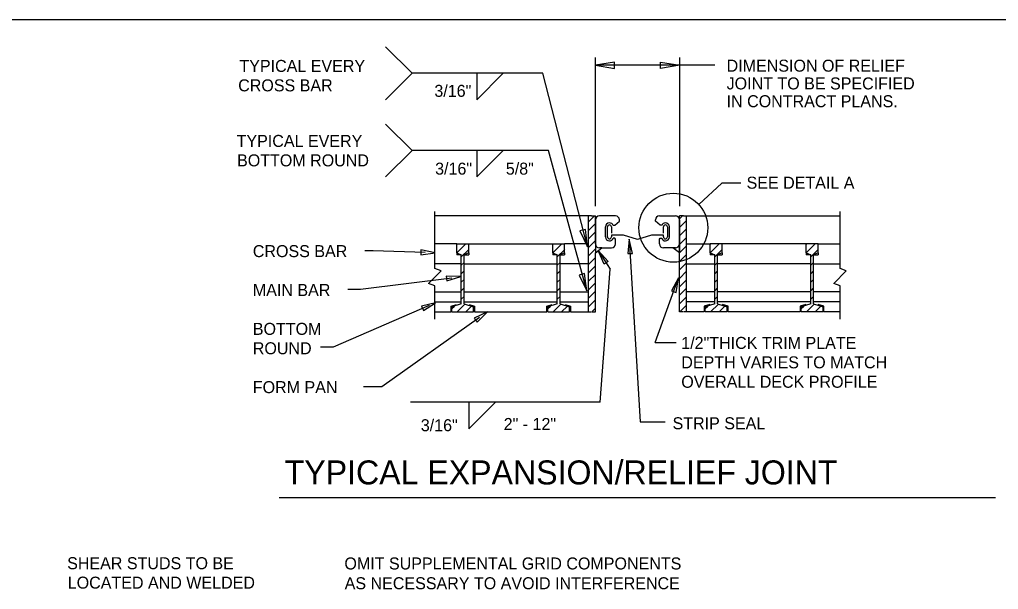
# Model space of a CAD drawing. Extents: x -24512 to -22484, y 4569 to 6351.
# Drawn here: x -24010.5 to -23765.7, y 5598.2 to 5740.6 of the extents above; entities that cross this region are included whole.
import ezdxf

# ---------------------------------------------------------------- set-up
doc = ezdxf.new("R2010")
doc.units = 0
for name, color, linetype in [('10', 7, 'Continuous'), ('2', 7, 'Continuous'), ('3', 7, 'Continuous'), ('4', 7, 'Continuous'), ('9', 7, 'Continuous'), ('PLT-BNDY', 7, 'Continuous')]:
    doc.layers.add(name, color=color, linetype=linetype)

# ---------------------------------------------------------------- blocks, each defined once
blk = doc.blocks.new('SYM026')
at = {"layer": '3'}
for p, q in [((45.29725, 11.51025), (45.748875, 11.96175)), ((45.29725, 11.937875), (45.32125, 11.96175)), ((45.52425, 11.3095), (45.8965, 11.68175)), ((45.52425, 10.881875), (45.6695, 11.027)), ((45.52425, 10.454125), (45.6695, 10.599375)), ((45.52425, 10.0265), (45.6695, 10.171625)), ((45.52425, 9.59875), (45.6695, 9.744)), ((45.31525, 8.534375), (45.7065, 8.925625)), ((45.52425, 9.171125), (45.6695, 9.31625)), ((45.04875, 8.6955), (45.18175, 8.8285)), ((45.743, 8.534375), (46.031, 8.8225))]:
    blk.add_line(p, q, dxfattribs=at)

msp = doc.modelspace()

# ---------------------------------------------------------------- linework, layer by layer
at = {"layer": '10'}
for p, q in [((-23840.65, 5694.43), (-23834.85, 5699.76)), ((-23866.47, 5684.57), (-23866.47, 5682.32)), ((-23845.47, 5684.57), (-23845.47, 5682.32)), ((-23866.47, 5682.32), (-23864.86, 5683.57)), ((-23864.86, 5683.57), (-23865.47, 5683.57)), ((-23845.47, 5682.32), (-23847.08, 5683.57)), ((-23847.08, 5683.57), (-23846.47, 5683.57)), ((-23945.53, 5621.13), (-23766.44, 5621.13))]:
    msp.add_line(p, q, dxfattribs=at)
msp.add_circle((-23847, 5688.6), 8.62, dxfattribs=at)
for centre, start, end in [((-23865.47, 5684.57), 180, 270), ((-23846.47, 5684.57), 270, 0)]:
    msp.add_arc(centre, 1, start, end, dxfattribs=at)
at = {"layer": '2'}
msp.add_line((-24137.79, 5740.63), (-23353.75, 5740.63), dxfattribs=at)
at = {"layer": '3'}
for p, q in [((-23868.22, 5690.05), (-23866.7, 5691.57)), ((-23845.47, 5690.8), (-23844.7, 5691.57)), ((-23868.22, 5687.93), (-23866.47, 5689.68)), ((-23845.47, 5688.68), (-23843.72, 5690.43)), ((-23868.22, 5685.81), (-23866.47, 5687.56)), ((-23845.47, 5686.56), (-23843.72, 5688.31)), ((-23845.47, 5684.44), (-23843.72, 5686.19)), ((-23868.22, 5683.69), (-23866.47, 5685.44)), ((-23845.47, 5682.32), (-23843.72, 5684.07)), ((-23868.22, 5681.57), (-23866.47, 5683.32)), ((-23845.47, 5680.2), (-23843.72, 5681.95)), ((-23868.22, 5679.45), (-23866.47, 5681.2)), ((-23868.22, 5677.33), (-23866.47, 5679.08)), ((-23845.47, 5678.08), (-23843.72, 5679.83)), ((-23868.22, 5675.21), (-23866.47, 5676.95)), ((-23845.47, 5675.95), (-23843.72, 5677.71)), ((-23868.22, 5673.08), (-23866.47, 5674.83)), ((-23845.47, 5673.83), (-23843.72, 5675.58)), ((-23868.22, 5670.96), (-23866.47, 5672.71)), ((-23845.47, 5671.71), (-23843.72, 5673.46)), ((-23868.22, 5668.84), (-23866.47, 5670.59)), ((-23845.47, 5669.59), (-23843.72, 5671.34)), ((-23845.37, 5667.57), (-23843.72, 5669.22)), ((-23867.37, 5667.57), (-23866.47, 5668.47))]:
    msp.add_line(p, q, dxfattribs=at)
at = {"layer": '4'}
for p, q in [((-23867.47, 5691.57), (-23906.63, 5691.57)), ((-23868.22, 5667.57), (-23868.22, 5691.57)), ((-23867.47, 5691.57), (-23866.47, 5691.57)), ((-23866.47, 5684.57), (-23866.47, 5691.57)), ((-23844.47, 5691.57), (-23845.47, 5691.57)), ((-23845.47, 5667.57), (-23845.47, 5691.57)), ((-23844.47, 5691.57), (-23805.3, 5691.57)), ((-23843.72, 5667.57), (-23843.72, 5691.57)), ((-23901.14, 5684.57), (-23906.63, 5684.57)), ((-23901.14, 5684.57), (-23898.17, 5684.57)), ((-23901.14, 5682.31), (-23901.14, 5684.57)), ((-23898.17, 5682.31), (-23898.17, 5684.57)), ((-23898.17, 5684.57), (-23877.14, 5684.57)), ((-23877.14, 5682.31), (-23877.14, 5684.57)), ((-23877.14, 5684.57), (-23874.17, 5684.57)), ((-23868.22, 5684.57), (-23874.17, 5684.57)), ((-23874.17, 5682.31), (-23874.17, 5684.57)), ((-23843.72, 5684.57), (-23837.77, 5684.57)), ((-23834.79, 5684.57), (-23837.77, 5684.57)), ((-23837.77, 5682.31), (-23837.77, 5684.57)), ((-23813.77, 5684.57), (-23834.79, 5684.57)), ((-23834.79, 5682.31), (-23834.79, 5684.57)), ((-23813.77, 5682.31), (-23813.77, 5684.57)), ((-23810.8, 5684.57), (-23813.77, 5684.57)), ((-23810.8, 5684.57), (-23805.3, 5684.57)), ((-23810.8, 5682.31), (-23810.8, 5684.57)), ((-23901.14, 5682.31), (-23900.01, 5681.81)), ((-23901.14, 5682.31), (-23901.14, 5681.81)), ((-23900.01, 5681.81), (-23901.14, 5681.81)), ((-23900.01, 5669.57), (-23900.01, 5681.81)), ((-23898.17, 5682.31), (-23899.29, 5681.81)), ((-23899.29, 5669.57), (-23899.29, 5681.81)), ((-23899.29, 5681.81), (-23898.17, 5681.81)), ((-23898.17, 5682.31), (-23898.17, 5681.81)), ((-23877.14, 5682.31), (-23876.01, 5681.81)), ((-23877.14, 5682.31), (-23877.14, 5681.81)), ((-23876.01, 5681.81), (-23877.14, 5681.81)), ((-23876.01, 5669.57), (-23876.01, 5681.81)), ((-23874.17, 5682.31), (-23875.29, 5681.81)), ((-23875.29, 5681.81), (-23874.17, 5681.81)), ((-23875.29, 5669.57), (-23875.29, 5681.81)), ((-23874.17, 5682.31), (-23874.17, 5681.81)), ((-23866.47, 5667.57), (-23866.47, 5682.32)), ((-23837.77, 5682.31), (-23836.64, 5681.81)), ((-23837.77, 5682.31), (-23837.77, 5681.81)), ((-23836.64, 5681.81), (-23837.77, 5681.81)), ((-23836.64, 5669.57), (-23836.64, 5681.81)), ((-23834.79, 5682.31), (-23835.92, 5681.81)), ((-23835.92, 5681.81), (-23834.79, 5681.81)), ((-23835.92, 5669.57), (-23835.92, 5681.81)), ((-23834.79, 5682.31), (-23834.79, 5681.81)), ((-23813.77, 5682.31), (-23813.77, 5681.81)), ((-23813.77, 5682.31), (-23812.64, 5681.81)), ((-23812.64, 5681.81), (-23813.77, 5681.81)), ((-23812.64, 5669.57), (-23812.64, 5681.81)), ((-23810.8, 5682.31), (-23811.92, 5681.81)), ((-23811.92, 5681.81), (-23810.8, 5681.81)), ((-23811.92, 5669.57), (-23811.92, 5681.81)), ((-23810.8, 5682.31), (-23810.8, 5681.81)), ((-23900.01, 5679.57), (-23906.63, 5679.57)), ((-23899.29, 5679.57), (-23876.01, 5679.57)), ((-23868.22, 5679.57), (-23875.29, 5679.57)), ((-23843.72, 5679.57), (-23836.64, 5679.57)), ((-23812.64, 5679.57), (-23835.92, 5679.57)), ((-23811.92, 5679.57), (-23805.3, 5679.57)), ((-23866.47, 5672.98), (-23866.47, 5676.98)), ((-23906.63, 5672.61), (-23900.01, 5672.61)), ((-23906.63, 5665.74), (-23906.63, 5672.61)), ((-23899.29, 5672.61), (-23876.01, 5672.61)), ((-23875.29, 5672.61), (-23868.22, 5672.61)), ((-23836.64, 5672.61), (-23843.72, 5672.61)), ((-23812.64, 5672.61), (-23835.92, 5672.61)), ((-23805.3, 5672.61), (-23811.92, 5672.61)), ((-23805.3, 5665.74), (-23805.3, 5672.61)), ((-23906.63, 5670.11), (-23900.01, 5670.11)), ((-23900.01, 5669.57), (-23902.37, 5668.82)), ((-23899.29, 5670.11), (-23876.01, 5670.11)), ((-23899.29, 5669.57), (-23896.94, 5668.82)), ((-23876.01, 5669.57), (-23878.37, 5668.82)), ((-23875.29, 5670.11), (-23868.22, 5670.11)), ((-23875.29, 5669.57), (-23872.94, 5668.82)), ((-23836.64, 5670.11), (-23843.72, 5670.11)), ((-23836.64, 5669.57), (-23839, 5668.82)), ((-23812.64, 5670.11), (-23835.92, 5670.11)), ((-23835.92, 5669.57), (-23833.56, 5668.82)), ((-23812.64, 5669.57), (-23815, 5668.82)), ((-23805.3, 5670.11), (-23811.92, 5670.11)), ((-23811.92, 5669.57), (-23809.56, 5668.82)), ((-23902.37, 5667.57), (-23902.37, 5668.82)), ((-23902.37, 5667.57), (-23896.94, 5667.57)), ((-23896.94, 5667.57), (-23896.94, 5668.82)), ((-23878.37, 5667.57), (-23878.37, 5668.82)), ((-23878.37, 5667.57), (-23872.94, 5667.57)), ((-23872.94, 5667.57), (-23872.94, 5668.82)), ((-23867.47, 5667.57), (-23866.47, 5667.57)), ((-23844.47, 5667.57), (-23845.47, 5667.57)), ((-23839, 5667.57), (-23839, 5668.82)), ((-23833.56, 5667.57), (-23839, 5667.57)), ((-23833.56, 5667.57), (-23833.56, 5668.82)), ((-23815, 5667.57), (-23815, 5668.82)), ((-23809.56, 5667.57), (-23815, 5667.57)), ((-23809.56, 5667.57), (-23809.56, 5668.82))]:
    msp.add_line(p, q, dxfattribs=at)
for points in [[(-23906.63, 5672.61), (-23906.63, 5674.05), (-23908.18, 5674.7), (-23905.08, 5677.8), (-23906.63, 5678.44), (-23906.63, 5692.67)], [(-23805.3, 5672.61), (-23805.3, 5674.05), (-23806.86, 5674.7), (-23803.75, 5677.8), (-23805.3, 5678.44), (-23805.3, 5692.67)], [(-23906.63, 5667.57), (-23902.54, 5667.57), (-23902.54, 5669), (-23901.19, 5669.43)], [(-23898.04, 5669.43), (-23896.69, 5669), (-23896.69, 5667.57), (-23878.62, 5667.57), (-23878.62, 5669), (-23877.27, 5669.43)], [(-23874.04, 5669.43), (-23872.69, 5669), (-23872.69, 5667.57), (-23867.63, 5667.57)], [(-23837.9, 5669.43), (-23839.25, 5669), (-23839.25, 5667.57), (-23844.31, 5667.57)], [(-23813.9, 5669.43), (-23815.25, 5669), (-23815.25, 5667.57), (-23833.31, 5667.57), (-23833.31, 5669), (-23834.67, 5669.43)], [(-23805.3, 5667.57), (-23809.39, 5667.57), (-23809.39, 5669), (-23810.75, 5669.43)]]:
    msp.add_lwpolyline(points, dxfattribs=at)
at = {"layer": '9'}
for p, q in [((-23918.94, 5733.83), (-23912.32, 5727.21)), ((-23866.47, 5693.97), (-23866.47, 5731.19)), ((-23845.37, 5693.97), (-23845.37, 5731.19)), ((-23836.59, 5729.21), (-23866.47, 5729.21)), ((-23918.94, 5720.59), (-23912.32, 5727.21)), ((-23879.65, 5727.21), (-23912.32, 5727.21)), ((-23896.17, 5720.59), (-23889.55, 5727.21)), ((-23896.17, 5727.21), (-23896.17, 5720.59)), ((-23868.49, 5683.84), (-23879.65, 5727.21)), ((-23918.94, 5714.53), (-23912.32, 5707.91)), ((-23918.94, 5701.29), (-23912.32, 5707.91)), ((-23878.18, 5707.91), (-23912.32, 5707.91)), ((-23896.17, 5707.91), (-23896.17, 5701.29)), ((-23896.17, 5701.29), (-23889.55, 5707.91)), ((-23868.62, 5672.81), (-23878.18, 5707.91)), ((-23830.09, 5699.76), (-23834.85, 5699.76)), ((-23858, 5685.76), (-23855.32, 5640.06)), ((-23922.06, 5682.85), (-23924.18, 5682.85)), ((-23909.03, 5682.4), (-23922.06, 5682.85)), ((-23865.76, 5682.87), (-23862.76, 5678.22)), ((-23865.3, 5644.98), (-23862.76, 5678.22)), ((-23902.4, 5676.02), (-23925.24, 5673.14)), ((-23851.57, 5659.89), (-23845.7, 5676.05)), ((-23925.24, 5673.14), (-23928.42, 5673.14)), ((-23908.05, 5669.16), (-23932.07, 5658.72)), ((-23895.46, 5666.18), (-23919.93, 5648.85)), ((-23851.57, 5659.89), (-23846.25, 5659.89)), ((-23932.07, 5658.72), (-23935.26, 5658.72)), ((-23919.93, 5648.85), (-23924.49, 5648.85)), ((-23865.3, 5644.98), (-23912.75, 5644.98)), ((-23898.1, 5638.36), (-23891.48, 5644.98)), ((-23898.1, 5644.98), (-23898.1, 5638.36)), ((-23855.32, 5640.06), (-23849.07, 5640.06))]:
    msp.add_line(p, q, dxfattribs=at)
for points in [[(-23861.67, 5728.41), (-23861.67, 5730.01), (-23866.47, 5729.21)], [(-23850.17, 5728.41), (-23850.17, 5730.01), (-23845.37, 5729.21)], [(-23868.95, 5688.19), (-23870.34, 5687.81), (-23868.49, 5683.84)], [(-23858.4, 5682.14), (-23857.2, 5682.2), (-23858, 5685.76)], [(-23910.11, 5683.04), (-23910.16, 5681.84), (-23906.54, 5682.31)], [(-23863.31, 5680.17), (-23864.31, 5679.52), (-23865.76, 5682.87)], [(-23903.79, 5676.52), (-23903.64, 5675.32), (-23900.14, 5676.37)], [(-23869.18, 5677.16), (-23870.56, 5676.74), (-23868.62, 5672.81)], [(-23847.43, 5672.84), (-23846.3, 5672.45), (-23845.7, 5676.05)], [(-23909.98, 5668.98), (-23909.51, 5667.88), (-23906.44, 5669.86)], [(-23896.78, 5665.98), (-23896.09, 5665), (-23893.5, 5667.57)]]:
    msp.add_lwpolyline(points, close=True, dxfattribs=at)
at = {"layer": 'PLT-BNDY'}
for p, q in [((-23861.47, 5691.57), (-23865.47, 5691.57)), ((-23850.47, 5691.57), (-23846.47, 5691.57)), ((-23866.47, 5690.57), (-23866.47, 5684.57)), ((-23863.97, 5686.32), (-23863.97, 5688.82)), ((-23863.47, 5686.32), (-23863.47, 5688.82)), ((-23862.47, 5688.82), (-23862.47, 5687.24)), ((-23862.04, 5689.2), (-23861.6, 5689.2)), ((-23861.6, 5689.2), (-23860.47, 5690.24)), ((-23860.47, 5690.24), (-23860.47, 5690.57)), ((-23851.47, 5690.24), (-23851.47, 5690.57)), ((-23850.33, 5689.2), (-23851.47, 5690.24)), ((-23849.9, 5689.2), (-23850.33, 5689.2)), ((-23849.47, 5687.24), (-23849.47, 5688.82)), ((-23848.47, 5688.82), (-23848.47, 5686.32)), ((-23847.97, 5686.32), (-23847.97, 5688.82)), ((-23845.47, 5690.57), (-23845.47, 5684.57)), ((-23859.47, 5686.74), (-23862.47, 5686.74)), ((-23862.47, 5686.74), (-23862.47, 5686.32)), ((-23855.97, 5685.62), (-23859.47, 5686.74)), ((-23852.46, 5686.74), (-23855.97, 5685.62)), ((-23849.47, 5686.74), (-23852.46, 5686.74)), ((-23849.47, 5686.32), (-23849.47, 5686.74)), ((-23861.6, 5685.95), (-23862.04, 5685.95)), ((-23861.47, 5685.78), (-23861.6, 5685.95)), ((-23861.47, 5684.57), (-23861.47, 5685.78)), ((-23850.47, 5685.78), (-23850.33, 5685.95)), ((-23850.47, 5684.57), (-23850.47, 5685.78)), ((-23850.33, 5685.95), (-23849.9, 5685.95)), ((-23864.86, 5683.57), (-23862.47, 5683.57)), ((-23846.47, 5683.57), (-23849.47, 5683.57))]:
    msp.add_line(p, q, dxfattribs=at)
for centre, radius, start, end in [((-23865.47, 5690.57), 1, 90, 180), ((-23861.47, 5690.57), 1, 0, 90), ((-23850.47, 5690.57), 1, 90, 180), ((-23846.47, 5690.57), 1, 0, 90), ((-23862.97, 5688.82), 1, 90, 180), ((-23862.97, 5688.82), 0.5, 90, 180), ((-23862.97, 5688.82), 1, 22.0033, 90), ((-23862.97, 5688.82), 0.5, 0, 90), ((-23848.97, 5688.82), 1, 90, 157.9967), ((-23848.97, 5688.82), 0.5, 90, 180), ((-23848.97, 5688.82), 1, 0, 90), ((-23848.97, 5688.82), 0.5, 0, 90), ((-23862.97, 5686.32), 1, 180, 270), ((-23862.97, 5686.32), 0.5, 180, 270), ((-23862.97, 5686.32), 0.5, 270, 0), ((-23848.97, 5686.32), 0.5, 180, 270), ((-23848.97, 5686.32), 0.5, 270, 0), ((-23848.97, 5686.32), 1, 270, 0), ((-23862.97, 5686.32), 1, 270, 337.9967), ((-23862.47, 5684.57), 1, 270, 0), ((-23849.47, 5684.57), 1, 180, 270), ((-23848.97, 5686.32), 1, 202.0033, 270), ((-23846.47, 5684.57), 1, 270, 0)]:
    msp.add_arc(centre, radius, start, end, dxfattribs=at)

# ---------------------------------------------------------------- block references
at = {"layer": '3', "xscale": 4.959971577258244, "yscale": 4.959971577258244}
for p in [(-24125.81, 5625.24), (-24101.81, 5625.24), (-24062.44, 5625.24), (-24038.44, 5625.24)]:
    msp.add_blockref('SYM026', p, dxfattribs=at)

# ---------------------------------------------------------------- texts
at = {"layer": '10'}
for s, height, p in [('5/8"', 3, (-23888.88, 5701.87)), ('TYPICAL EXPANSION/RELIEF JOINT', 6.0008, (-23944.18, 5624.43))]:
    msp.add_text(s, height=height, dxfattribs=at).set_placement(p)
at = {"layer": '9'}
for s, height, p in [('TYPICAL EVERY', 2.9999, (-23955.5, 5727.55)), ('DIMENSION OF RELIEF ', 2.9999, (-23833.67, 5727.61)), ('CROSS BAR', 3, (-23955.81, 5722.69)), ('JOINT TO BE SPECIFIED', 2.9999, (-23833.67, 5723.17)), ('3/16"', 3, (-23906.75, 5721.32)), ('IN CONTRACT PLANS.', 2.9999, (-23833.67, 5718.73)), ('TYPICAL EVERY', 2.9999, (-23956.2, 5708.8)), ('BOTTOM ROUND', 2.9999, (-23956.09, 5703.94)), ('3/16"', 3, (-23906.56, 5701.87)), ('SEE DETAIL A', 2.9999, (-23828.68, 5698.36)), ('CROSS BAR', 3, (-23952.15, 5681.25)), ('MAIN BAR', 3, (-23952.15, 5671.54)), ('BOTTOM', 3, (-23952.15, 5661.82)), ('ROUND', 3, (-23952.15, 5656.97)), ('1/2"THICK TRIM PLATE ', 2.9999, (-23845.01, 5658.31)), ('DEPTH VARIES TO MATCH', 2.9999, (-23845.01, 5653.45)), ('FORM PAN', 3, (-23952.15, 5647.25)), ('OVERALL DECK PROFILE', 2.9999, (-23845.01, 5648.59)), ('3/16"', 3, (-23910.14, 5637.73)), ('2" - 12"', 3, (-23889.42, 5638.04)), ('STRIP SEAL', 3, (-23847.19, 5638.22)), ('SHEAR STUDS TO BE', 2.9999, (-23998.58, 5603.24)), ('OMIT SUPPLEMENTAL GRID COMPONENTS', 2.9999, (-23929.25, 5603.17)), ('LOCATED AND WELDED', 2.9999, (-23998.43, 5598.38)), ('AS NECESSARY TO AVOID INTERFERENCE', 2.9999, (-23929.18, 5598.23))]:
    msp.add_text(s, height=height, dxfattribs=at).set_placement(p)

doc.saveas('drawing.dxf')
